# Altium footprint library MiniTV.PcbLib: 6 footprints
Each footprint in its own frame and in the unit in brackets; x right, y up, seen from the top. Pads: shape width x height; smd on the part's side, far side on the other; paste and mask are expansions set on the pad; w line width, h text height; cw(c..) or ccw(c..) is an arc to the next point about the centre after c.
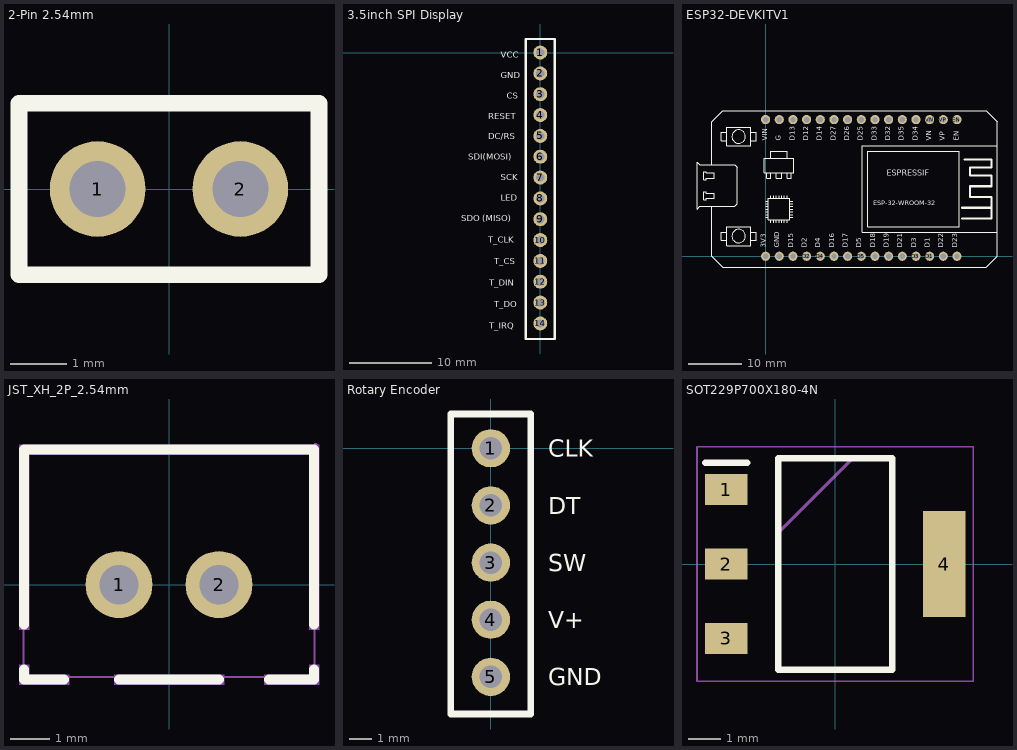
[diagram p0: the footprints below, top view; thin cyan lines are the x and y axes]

## 2-Pin 2.54mm [mm]
pads (2):
  round 1.7 hole 1 paste-2539.97 mask+0.051: 1(-1.27,0) 2(1.27,0)
Top Overlay:
  lines w0.3: -2.667,-1.524 -2.667,1.524 2.667,1.524 2.667,-1.524 -2.667,-1.524
Mechanical 15:
  region: -0.95,-0.32 -1.59,-0.32 -1.59,0.32 -0.95,0.32
  region: 1.59,-0.32 0.95,-0.32 0.95,0.32 1.59,0.32

## 3.5inch SPI Display [mm]
pads (14):
  round 1.7 hole 1: 1(0,0) 2(0,-2.54) 3(0,-5.08) 4(0,-7.62) 5(0,-10.16) 6(0,-12.7) 7(0,-15.24) 8(0,-17.78) 9(0,-20.32) 10(0,-22.86) 11(0,-25.4) 12(0,-27.94) 13(0,-30.48) 14(0,-33.02)
Top Overlay:
  lines w0.3: -1.778,-34.925 1.778,-34.925 1.778,1.651 -1.778,1.651 -1.778,-10.668 -1.778,-34.925
  text "T_IRQ" at -6.224,-33.655 h0.76
  text "T_DO" at -5.589,-31.037 h0.76
  text "T_DIN" at -6.224,-28.419 h0.76
  text "T_CS" at -5.589,-25.801 h0.76
  text "T_CLK" at -6.351,-23.183 h0.76
  text "SDO (MISO)" at -9.652,-20.564 h0.76
  text "LED" at -4.828,-18.073 h0.76
  text "SCK" at -4.828,-15.582 h0.76
  text "SDI(MOSI)" at -8.763,-13.091 h0.76
  text "DC/RS" at -6.351,-10.6 h0.76
  text "RESET" at -6.351,-8.109 h0.76
  text "CS" at -4.066,-5.617 h0.76
  text "GND" at -4.828,-3.126 h0.76
  text "VCC" at -4.828,-0.635 h0.76

## ESP32-DEVKITV1 [mm]
pads (30):
  round 1.7 hole 1: 3V3(0,0) D1(30.48,0) D2(7.62,0) D3(27.94,0) D4(10.16,0) D5(17.78,0) D12(7.62,25.4) D13(5.08,25.4) D14(10.16,25.4) D15(5.08,0) D16(12.7,0) D17(15.24,0) D18(20.32,0) D19(22.86,0) D21(25.4,0) D22(33.02,0) D23(35.56,0) D25(17.78,25.4) D26(15.24,25.4) D27(12.7,25.4) D32(22.86,25.4) D33(20.32,25.4) D34(27.94,25.4) D35(25.4,25.4) EN(35.56,25.4) GND(2.54,25.4) GND@1(2.54,0) VIN(0,25.4) VN(30.48,25.4) VP(33.02,25.4)
Top Overlay:
  drawing of 170 lines, arcs and shapes, not listed
  text "D35" at 26.07,21.47 h1.57
  text "D33" at 20.99,21.47 h1.57
  text "D25" at 18.45,21.47 h1.57
  text "D32" at 23.53,21.47 h1.57
  text "D34" at 28.61,21.47 h1.57
  text "VN" at 31.15,21.47 h1.57
  text "VP" at 33.69,21.47 h1.57
  text "EN" at 36.23,21.47 h1.57
  text "ESPRESSIF" at 22.5,15 h1.08
  text "D26" at 15.91,21.47 h1.57
  text "D13" at 5.75,21.47 h1.57
  text "D12" at 8.29,21.47 h1.57
  text "D27" at 13.37,21.47 h1.57
  text "D14" at 10.83,21.47 h1.57
  text "G" at 3.21,21.47 h1.57
  text "ESP-32-WROOM-32" at 20,9.5 h0.86
  text "D16" at 13.1,1.54 h1.57
  text "D19" at 23.26,1.54 h1.57
  text "D15" at 5.48,1.54 h1.57
  text "D23" at 35.96,1.54 h1.57
  text "D18" at 20.72,1.54 h1.57
  text "D21" at 25.8,1.54 h1.57
  text "D22" at 33.42,1.54 h1.57
  text "D17" at 15.64,1.54 h1.57
  text "D5" at 18.18,1.54 h1.57
  text "D3" at 28.34,1.54 h1.57
  text "D1" at 30.88,1.54 h1.57
  text "D2" at 8.02,1.54 h1.57
  text "D4" at 10.56,1.54 h1.57
  text "GND" at 2.94,1.54 h1.57
  text "VIN" at 0.67,21.47 h1.57
  text "3V3" at 0.4,1.54 h1.57
Mechanical 5:
  text "ESP32-DEVKITV1" at 26.36,-4.54 h1.97
Mechanical 8:
  text "ESP32-Devkit V1" at 28.92,12.31 h2.99

## JST_XH_2P_2.54mm [mm]
pads (2):
  round 1.7 hole 1 paste-2539.97 mask+0.051: 1(-1.27,0) 2(1.27,0)
Top Overlay:
  lines w0.254: -3.683,-2.159 -3.683,-2.413 -2.667,-2.413 ; -3.683,-1.016 -3.683,3.429 3.683,3.429 3.683,-1.016 ; -1.27,-2.413 1.27,-2.413 ; 2.54,-2.413 3.683,-2.413 3.683,-2.159
Mechanical 6:
  region: -3.81,-1.143 -3.81,3.556 3.81,3.556 3.81,-1.143 3.556,-1.143 3.556,3.302 -3.556,3.302 -3.556,-1.143
  region: -2.54,-2.54 -3.81,-2.54 -3.81,-2.032 -3.556,-2.032 -3.556,-2.286 -2.54,-2.286
  region: 2.413,-2.54 3.81,-2.54 3.81,-2.032 3.556,-2.032 3.556,-2.286 2.413,-2.286
  region: -1.397,-2.54 -1.397,-2.286 1.397,-2.286 1.397,-2.54
Mechanical 15:
  region: 1.59,-0.32 0.95,-0.32 0.95,0.32 1.59,0.32
  region: -0.95,-0.32 -1.59,-0.32 -1.59,0.32 -0.95,0.32
  region: 3.787,3.527 3.786,3.552 3.751,3.586 3.702,3.586 3.668,3.552 3.667,3.527 3.668,3.503 3.702,3.468 3.751,3.468 3.786,3.503
  lines w0.051: -3.7,-2.35 3.7,-2.35 3.7,3.4 -3.7,3.4 -3.7,-2.35

## Rotary Encoder [mm]
pads (5):
  round 1.7 hole 1: 1(0,0) 2(0,-2.54) 3(0,-5.08) 4(0,-7.62) 5(0,-10.16)
Top Overlay:
  lines w0.3: -1.778,-11.811 1.778,-11.811 1.778,1.524 -1.778,1.524 -1.778,-10.795 -1.778,-11.811
  text "CLK" at 2.541,-0.381 h0.76
  text "DT" at 2.541,-2.921 h0.76
  text "SW" at 2.541,-5.461 h0.76
  text "V+" at 2.541,-8.001 h0.76
  text "GND" at 2.541,-10.541 h0.76

## SOT229P700X180-4N [mm]
pads (4):
  rect 1.3x0.95 smd: 1(-3.35,2.29) 2(-3.35,0) 3(-3.35,-2.29)
  rect 1.3x3.25 smd: 4(3.35,0)
Top Overlay:
  lines w0.2: -4,3.115 -2.7,3.115 ; -1.752,-3.252 -1.752,3.252 1.752,3.252 1.752,-3.252 -1.752,-3.252
Mechanical 13:
  lines w0.1: -1.752,0.962 0.538,3.252 ; -1.752,-3.252 -1.752,3.252 1.752,3.252 1.752,-3.252 -1.752,-3.252
Mechanical 15:
  lines w0.05: -4.25,-3.605 -4.25,3.605 4.25,3.605 4.25,-3.605 -4.25,-3.605
3D body "AMS1117-3.3.stp": height 1.8, standoff 0, extent -3.5,-3.253 3.5,3.253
